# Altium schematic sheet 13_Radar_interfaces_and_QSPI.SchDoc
size 289 x 575 mm
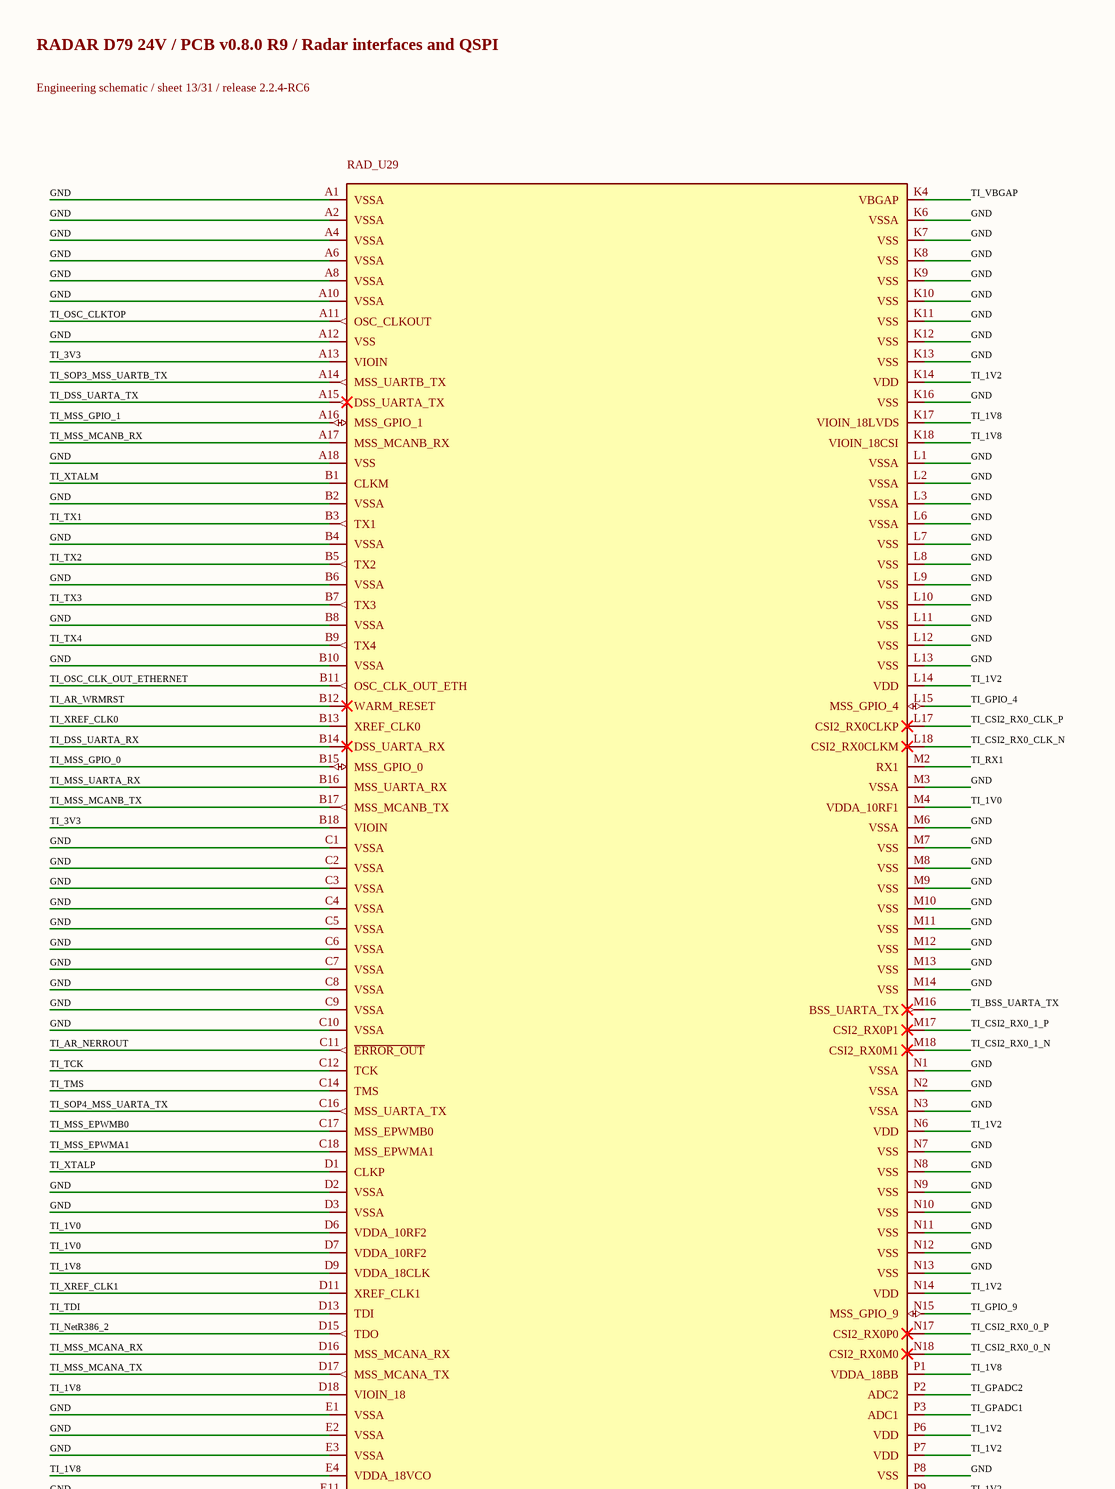
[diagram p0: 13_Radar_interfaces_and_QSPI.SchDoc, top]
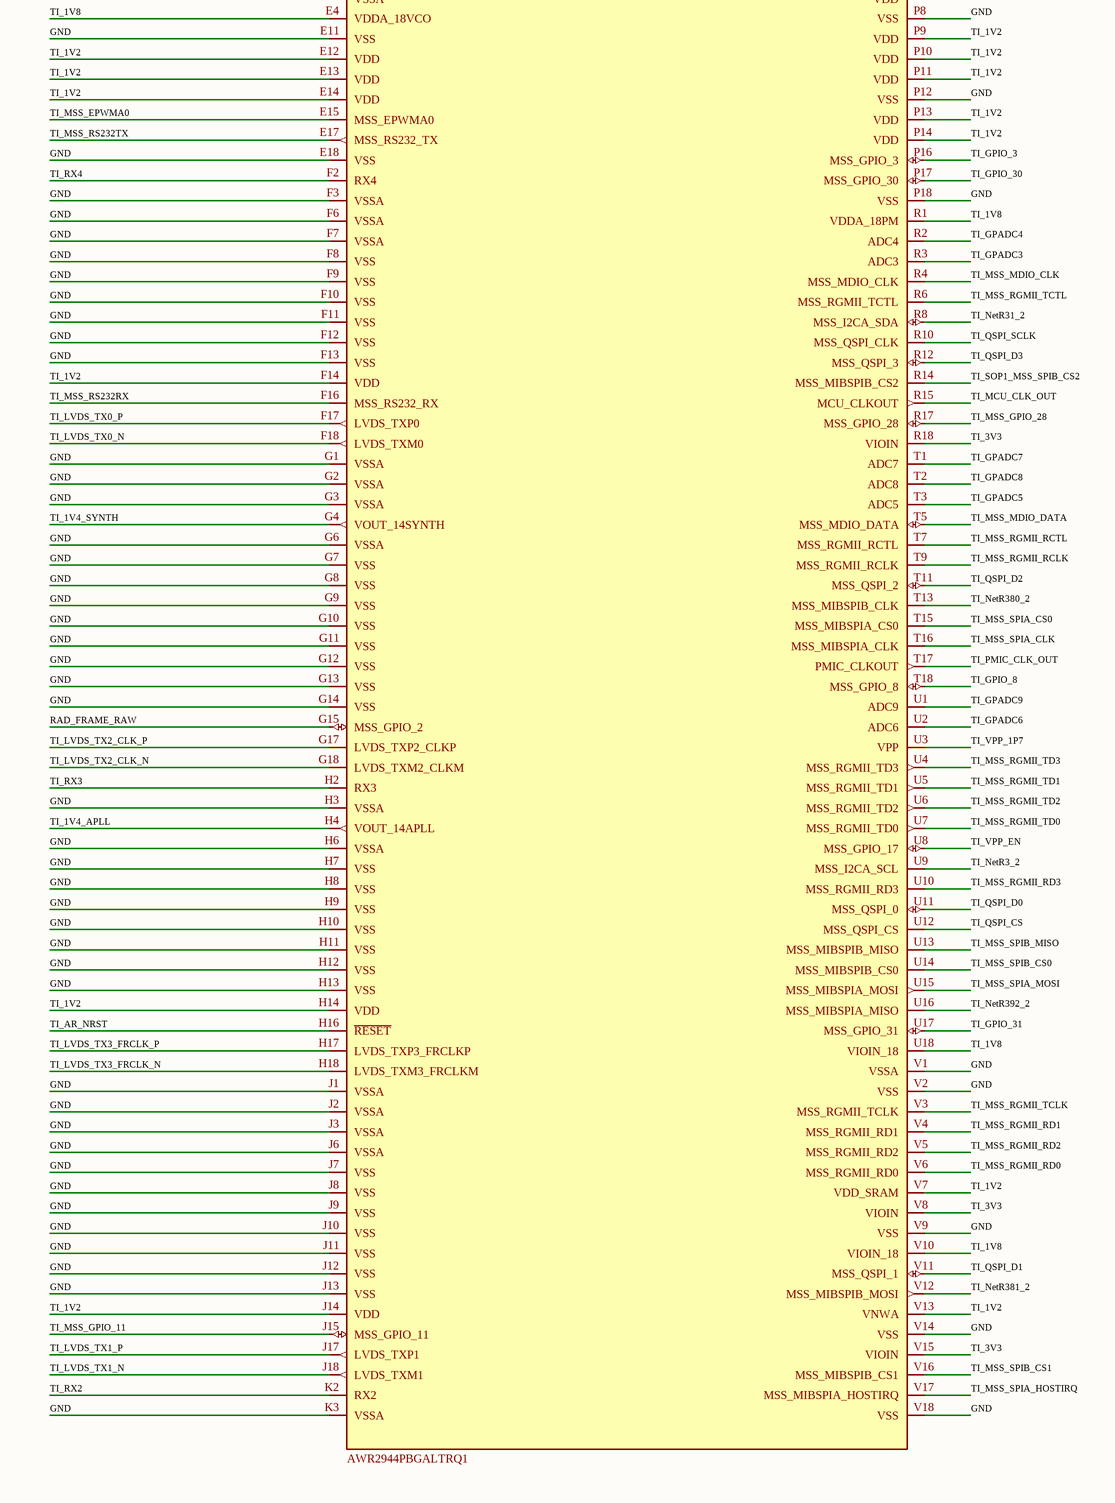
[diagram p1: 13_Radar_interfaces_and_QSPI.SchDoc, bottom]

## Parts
RAD_U29  AWR2944PBGALTRQ1  [ALT0266A-MFG]

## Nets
GND: RAD_U29.A1(VSSA) RAD_U29.A2(VSSA) RAD_U29.A4(VSSA) RAD_U29.A6(VSSA) RAD_U29.A8(VSSA) RAD_U29.A10(VSSA) RAD_U29.A12(VSS) RAD_U29.A18(VSS) RAD_U29.B2(VSSA) RAD_U29.B4(VSSA) RAD_U29.B6(VSSA) RAD_U29.B8(VSSA) RAD_U29.B10(VSSA) RAD_U29.C1(VSSA) RAD_U29.C2(VSSA) RAD_U29.C3(VSSA) RAD_U29.C4(VSSA) RAD_U29.C5(VSSA) RAD_U29.C6(VSSA) RAD_U29.C7(VSSA) RAD_U29.C8(VSSA) RAD_U29.C9(VSSA) RAD_U29.C10(VSSA) RAD_U29.D2(VSSA) RAD_U29.D3(VSSA) RAD_U29.E1(VSSA) RAD_U29.E2(VSSA) RAD_U29.E3(VSSA) RAD_U29.E11(VSS) RAD_U29.E18(VSS) RAD_U29.F3(VSSA) RAD_U29.F6(VSSA) RAD_U29.F7(VSSA) RAD_U29.F8(VSS) RAD_U29.F9(VSS) RAD_U29.F10(VSS) RAD_U29.F11(VSS) RAD_U29.F12(VSS) RAD_U29.F13(VSS) RAD_U29.G1(VSSA) RAD_U29.G2(VSSA) RAD_U29.G3(VSSA) RAD_U29.G6(VSSA) RAD_U29.G7(VSS) RAD_U29.G8(VSS) RAD_U29.G9(VSS) RAD_U29.G10(VSS) RAD_U29.G11(VSS) RAD_U29.G12(VSS) RAD_U29.G13(VSS) RAD_U29.G14(VSS) RAD_U29.H3(VSSA) RAD_U29.H6(VSSA) RAD_U29.H7(VSS) RAD_U29.H8(VSS) RAD_U29.H9(VSS) RAD_U29.H10(VSS) RAD_U29.H11(VSS) RAD_U29.H12(VSS) RAD_U29.H13(VSS) RAD_U29.J1(VSSA) RAD_U29.J2(VSSA) RAD_U29.J3(VSSA) RAD_U29.J6(VSSA) RAD_U29.J7(VSS) RAD_U29.J8(VSS) RAD_U29.J9(VSS) RAD_U29.J10(VSS) RAD_U29.J11(VSS) RAD_U29.J12(VSS) RAD_U29.J13(VSS) RAD_U29.K3(VSSA) RAD_U29.K6(VSSA) RAD_U29.K7(VSS) RAD_U29.K8(VSS) RAD_U29.K9(VSS) RAD_U29.K10(VSS) RAD_U29.K11(VSS) RAD_U29.K12(VSS) RAD_U29.K13(VSS) RAD_U29.K16(VSS) RAD_U29.L1(VSSA) RAD_U29.L2(VSSA) RAD_U29.L3(VSSA) RAD_U29.L6(VSSA) RAD_U29.L7(VSS) RAD_U29.L8(VSS) RAD_U29.L9(VSS) RAD_U29.L10(VSS) RAD_U29.L11(VSS) RAD_U29.L12(VSS) RAD_U29.L13(VSS) RAD_U29.M3(VSSA) RAD_U29.M6(VSSA) RAD_U29.M7(VSS) RAD_U29.M8(VSS) RAD_U29.M9(VSS) RAD_U29.M10(VSS) RAD_U29.M11(VSS) RAD_U29.M12(VSS) RAD_U29.M13(VSS) RAD_U29.M14(VSS) RAD_U29.N1(VSSA) RAD_U29.N2(VSSA) RAD_U29.N3(VSSA) RAD_U29.N7(VSS) RAD_U29.N8(VSS) RAD_U29.N9(VSS) RAD_U29.N10(VSS) RAD_U29.N11(VSS) RAD_U29.N12(VSS) RAD_U29.N13(VSS) RAD_U29.P8(VSS) RAD_U29.P12(VSS) RAD_U29.P18(VSS) RAD_U29.V1(VSSA) RAD_U29.V2(VSS) RAD_U29.V9(VSS) RAD_U29.V14(VSS) RAD_U29.V18(VSS)
RAD_FRAME_RAW: RAD_U29.G15(MSS_GPIO_2)
TI_1V0: RAD_U29.D6(VDDA_10RF2) RAD_U29.D7(VDDA_10RF2) RAD_U29.M4(VDDA_10RF1)
TI_1V2: RAD_U29.E12(VDD) RAD_U29.E13(VDD) RAD_U29.E14(VDD) RAD_U29.F14(VDD) RAD_U29.H14(VDD) RAD_U29.J14(VDD) RAD_U29.K14(VDD) RAD_U29.L14(VDD) RAD_U29.N6(VDD) RAD_U29.N14(VDD) RAD_U29.P6(VDD) RAD_U29.P7(VDD) RAD_U29.P9(VDD) RAD_U29.P10(VDD) RAD_U29.P11(VDD) RAD_U29.P13(VDD) RAD_U29.P14(VDD) RAD_U29.V7(VDD_SRAM) RAD_U29.V13(VNWA)
TI_1V4_APLL: RAD_U29.H4(VOUT_14APLL)
TI_1V4_SYNTH: RAD_U29.G4(VOUT_14SYNTH)
TI_1V8: RAD_U29.D9(VDDA_18CLK) RAD_U29.D18(VIOIN_18) RAD_U29.E4(VDDA_18VCO) RAD_U29.K17(VIOIN_18LVDS) RAD_U29.K18(VIOIN_18CSI) RAD_U29.P1(VDDA_18BB) RAD_U29.R1(VDDA_18PM) RAD_U29.U18(VIOIN_18) RAD_U29.V10(VIOIN_18)
TI_3V3: RAD_U29.A13(VIOIN) RAD_U29.B18(VIOIN) RAD_U29.R18(VIOIN) RAD_U29.V8(VIOIN) RAD_U29.V15(VIOIN)
TI_AR_NERROUT: RAD_U29.C11(~{ERROR_OUT})
TI_AR_NRST: RAD_U29.H16(~{RESET})
TI_AR_WRMRST: RAD_U29.B12(WARM_RESET)
TI_BSS_UARTA_TX: RAD_U29.M16(BSS_UARTA_TX)
TI_CSI2_RX0_0_N: RAD_U29.N18(CSI2_RX0M0)
TI_CSI2_RX0_0_P: RAD_U29.N17(CSI2_RX0P0)
TI_CSI2_RX0_1_N: RAD_U29.M18(CSI2_RX0M1)
TI_CSI2_RX0_1_P: RAD_U29.M17(CSI2_RX0P1)
TI_CSI2_RX0_CLK_N: RAD_U29.L18(CSI2_RX0CLKM)
TI_CSI2_RX0_CLK_P: RAD_U29.L17(CSI2_RX0CLKP)
TI_DSS_UARTA_RX: RAD_U29.B14(DSS_UARTA_RX)
TI_DSS_UARTA_TX: RAD_U29.A15(DSS_UARTA_TX)
TI_GPADC1: RAD_U29.P3(ADC1)
TI_GPADC2: RAD_U29.P2(ADC2)
TI_GPADC3: RAD_U29.R3(ADC3)
TI_GPADC4: RAD_U29.R2(ADC4)
TI_GPADC5: RAD_U29.T3(ADC5)
TI_GPADC6: RAD_U29.U2(ADC6)
TI_GPADC7: RAD_U29.T1(ADC7)
TI_GPADC8: RAD_U29.T2(ADC8)
TI_GPADC9: RAD_U29.U1(ADC9)
TI_GPIO_3: RAD_U29.P16(MSS_GPIO_3)
TI_GPIO_4: RAD_U29.L15(MSS_GPIO_4)
TI_GPIO_8: RAD_U29.T18(MSS_GPIO_8)
TI_GPIO_9: RAD_U29.N15(MSS_GPIO_9)
TI_GPIO_30: RAD_U29.P17(MSS_GPIO_30)
TI_GPIO_31: RAD_U29.U17(MSS_GPIO_31)
TI_LVDS_TX0_N: RAD_U29.F18(LVDS_TXM0)
TI_LVDS_TX0_P: RAD_U29.F17(LVDS_TXP0)
TI_LVDS_TX1_N: RAD_U29.J18(LVDS_TXM1)
TI_LVDS_TX1_P: RAD_U29.J17(LVDS_TXP1)
TI_LVDS_TX2_CLK_N: RAD_U29.G18(LVDS_TXM2_CLKM)
TI_LVDS_TX2_CLK_P: RAD_U29.G17(LVDS_TXP2_CLKP)
TI_LVDS_TX3_FRCLK_N: RAD_U29.H18(LVDS_TXM3_FRCLKM)
TI_LVDS_TX3_FRCLK_P: RAD_U29.H17(LVDS_TXP3_FRCLKP)
TI_MCU_CLK_OUT: RAD_U29.R15(MCU_CLKOUT)
TI_MSS_EPWMA0: RAD_U29.E15(MSS_EPWMA0)
TI_MSS_EPWMA1: RAD_U29.C18(MSS_EPWMA1)
TI_MSS_EPWMB0: RAD_U29.C17(MSS_EPWMB0)
TI_MSS_GPIO_0: RAD_U29.B15(MSS_GPIO_0)
TI_MSS_GPIO_1: RAD_U29.A16(MSS_GPIO_1)
TI_MSS_GPIO_11: RAD_U29.J15(MSS_GPIO_11)
TI_MSS_GPIO_28: RAD_U29.R17(MSS_GPIO_28)
TI_MSS_MCANA_RX: RAD_U29.D16(MSS_MCANA_RX)
TI_MSS_MCANA_TX: RAD_U29.D17(MSS_MCANA_TX)
TI_MSS_MCANB_RX: RAD_U29.A17(MSS_MCANB_RX)
TI_MSS_MCANB_TX: RAD_U29.B17(MSS_MCANB_TX)
TI_MSS_MDIO_CLK: RAD_U29.R4(MSS_MDIO_CLK)
TI_MSS_MDIO_DATA: RAD_U29.T5(MSS_MDIO_DATA)
TI_MSS_RGMII_RCLK: RAD_U29.T9(MSS_RGMII_RCLK)
TI_MSS_RGMII_RCTL: RAD_U29.T7(MSS_RGMII_RCTL)
TI_MSS_RGMII_RD0: RAD_U29.V6(MSS_RGMII_RD0)
TI_MSS_RGMII_RD1: RAD_U29.V4(MSS_RGMII_RD1)
TI_MSS_RGMII_RD2: RAD_U29.V5(MSS_RGMII_RD2)
TI_MSS_RGMII_RD3: RAD_U29.U10(MSS_RGMII_RD3)
TI_MSS_RGMII_TCLK: RAD_U29.V3(MSS_RGMII_TCLK)
TI_MSS_RGMII_TCTL: RAD_U29.R6(MSS_RGMII_TCTL)
TI_MSS_RGMII_TD0: RAD_U29.U7(MSS_RGMII_TD0)
TI_MSS_RGMII_TD1: RAD_U29.U5(MSS_RGMII_TD1)
TI_MSS_RGMII_TD2: RAD_U29.U6(MSS_RGMII_TD2)
TI_MSS_RGMII_TD3: RAD_U29.U4(MSS_RGMII_TD3)
TI_MSS_RS232RX: RAD_U29.F16(MSS_RS232_RX)
TI_MSS_RS232TX: RAD_U29.E17(MSS_RS232_TX)
TI_MSS_SPIA_CLK: RAD_U29.T16(MSS_MIBSPIA_CLK)
TI_MSS_SPIA_CS0: RAD_U29.T15(MSS_MIBSPIA_CS0)
TI_MSS_SPIA_HOSTIRQ: RAD_U29.V17(MSS_MIBSPIA_HOSTIRQ)
TI_MSS_SPIA_MOSI: RAD_U29.U15(MSS_MIBSPIA_MOSI)
TI_MSS_SPIB_CS0: RAD_U29.U14(MSS_MIBSPIB_CS0)
TI_MSS_SPIB_CS1: RAD_U29.V16(MSS_MIBSPIB_CS1)
TI_MSS_SPIB_MISO: RAD_U29.U13(MSS_MIBSPIB_MISO)
TI_MSS_UARTA_RX: RAD_U29.B16(MSS_UARTA_RX)
TI_NetR3_2: RAD_U29.U9(MSS_I2CA_SCL)
TI_NetR31_2: RAD_U29.R8(MSS_I2CA_SDA)
TI_NetR380_2: RAD_U29.T13(MSS_MIBSPIB_CLK)
TI_NetR381_2: RAD_U29.V12(MSS_MIBSPIB_MOSI)
TI_NetR386_2: RAD_U29.D15(TDO)
TI_NetR392_2: RAD_U29.U16(MSS_MIBSPIA_MISO)
TI_OSC_CLK_OUT_ETHERNET: RAD_U29.B11(OSC_CLK_OUT_ETH)
TI_OSC_CLKTOP: RAD_U29.A11(OSC_CLKOUT)
TI_PMIC_CLK_OUT: RAD_U29.T17(PMIC_CLKOUT)
TI_QSPI_CS: RAD_U29.U12(MSS_QSPI_CS)
TI_QSPI_D0: RAD_U29.U11(MSS_QSPI_0)
TI_QSPI_D1: RAD_U29.V11(MSS_QSPI_1)
TI_QSPI_D2: RAD_U29.T11(MSS_QSPI_2)
TI_QSPI_D3: RAD_U29.R12(MSS_QSPI_3)
TI_QSPI_SCLK: RAD_U29.R10(MSS_QSPI_CLK)
TI_RX1: RAD_U29.M2(RX1)
TI_RX2: RAD_U29.K2(RX2)
TI_RX3: RAD_U29.H2(RX3)
TI_RX4: RAD_U29.F2(RX4)
TI_SOP1_MSS_SPIB_CS2: RAD_U29.R14(MSS_MIBSPIB_CS2)
TI_SOP3_MSS_UARTB_TX: RAD_U29.A14(MSS_UARTB_TX)
TI_SOP4_MSS_UARTA_TX: RAD_U29.C16(MSS_UARTA_TX)
TI_TCK: RAD_U29.C12(TCK)
TI_TDI: RAD_U29.D13(TDI)
TI_TMS: RAD_U29.C14(TMS)
TI_TX1: RAD_U29.B3(TX1)
TI_TX2: RAD_U29.B5(TX2)
TI_TX3: RAD_U29.B7(TX3)
TI_TX4: RAD_U29.B9(TX4)
TI_VBGAP: RAD_U29.K4(VBGAP)
TI_VPP_1P7: RAD_U29.U3(VPP)
TI_VPP_EN: RAD_U29.U8(MSS_GPIO_17)
TI_XREF_CLK0: RAD_U29.B13(XREF_CLK0)
TI_XREF_CLK1: RAD_U29.D11(XREF_CLK1)
TI_XTALM: RAD_U29.B1(CLKM)
TI_XTALP: RAD_U29.D1(CLKP)

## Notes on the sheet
- RADAR D79 24V / PCB v0.8.0 R9 / Radar interfaces and QSPI
- Engineering schematic / sheet 13/31 / release 2.2.4-RC6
